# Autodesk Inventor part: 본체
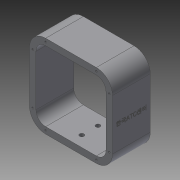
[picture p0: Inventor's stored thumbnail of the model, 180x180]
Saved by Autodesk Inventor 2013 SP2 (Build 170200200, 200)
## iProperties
Created: 2016-12
Part Number: 본체
Material: 일반
Document SubType Name: Modeling
Designer: mduedu
Density: 1 g/cm^3
Author: mduedu
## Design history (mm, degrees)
sketch "스케치1"
  geometry: L1 (-54, 50)-(-54, -44); L2 (-24, 80)-(70, 80); L3 (100, 50)-(100, -44); L4 (70, -74)-(-24, -74); A1 r 30 centre (-24, -44) between (-54, -44) and (-24, -74); A2 r 30 centre (70, 50) between (100, 50) and (70, 80); A3 r 30 centre (70, -44) between (70, -74) and (100, -44); A4 r 30 centre (-24, 50) between (-24, 80) and (-54, 50); 1 further point
  constraints: 8 end point, 8 point on circle, 8 tangent, 4 centre point, 3 equal radius, 2 perpendicular, 1 horizontal, 1 vertical
  dimensions: "d83" = 30 radius of A2; "d84" = 100 distance from line of L3 point (0, 0); "d85" = 154 distance between parallel lines of L4 L2; "d87" = 80 distance from line of point (0, 0) L2
extrude "돌출1" new body sketch "스케치1" stored distance "d3" = 70; taper "d4" = 0 deg
feature "쉘1" dims "d5" = 12
sketch "스케치10"
  geometry: 2 further points
  constraints: 1 coincident, 1 other
feature "엠보싱1" sketch "스케치10" dims "d61" = 0.5, "d62" = 0
sketch "스케치11"
  geometry: L1 (-42, -44)-(-42, 50) reference; L2 (-24, 68)-(70, 68) reference; L3 (88, 50)-(88, -44) reference; L4 (70, -62)-(-24, -62) reference; L5 (-24, -74)-(70, -74) reference; L6 (100, -44)-(100, 50) reference; L7 (70, 80)-(-24, 80) reference; L8 (-54, 50)-(-54, -44) reference; L9 (-24, 74)-(70, 74); L10 (94, 50)-(94, -44); L11 (70, -68)-(-24, -68); L12 (-48, -44)-(-48, 50); A1 r 18 centre (-24, -44) between (-42, -44) and (-24, -62) reference; A2 r 18 centre (-24, 50) between (-24, 68) and (-42, 50) reference; A3 r 18 centre (70, 50) between (88, 50) and (70, 68) reference; A4 r 18 centre (70, -44) between (70, -62) and (88, -44) reference; A5 r 30 centre (-24, -44) between (-54, -44) and (-24, -74) reference; A6 r 30 centre (70, -44) between (70, -74) and (100, -44) reference; A7 r 30 centre (70, 50) between (100, 50) and (70, 80) reference; A8 r 30 centre (-24, 50) between (-24, 80) and (-54, 50) reference; A9 r 24 centre (70, 50) between (94, 50) and (70, 74); A10 r 24 centre (70, -44) between (70, -68) and (94, -44); A11 r 24 centre (-24, -44) between (-48, -44) and (-24, -68); A12 r 24 centre (-24, 50) between (-24, 74) and (-48, 50); 8 further points
  constraints: 8 coincident, 8 end point, 8 point on circle, 4 centre point, 7 other
  dimensions: "d90" = 6 distance between parallel lines of L9 L7
hole "구멍3" sketch "스케치11" at (-24, 74), (-48, 50), (-48, -44), (-24, -68), (70, -68), (94, -44), (94, 50), (70, 74) diameter "d63" = 3.242; stored, may be unused: countersink angle "d67" = 90 deg, drill point angle "d69" = 120 deg; dims "d64" = 8.6, "d65" = 4, "d66" = 2, "d68" = 10.6
sketch "스케치12"
  geometry: L1 (24, -62)-(-70, -62) reference; L2 (-88, -44)-(-88, 50) reference; L3 (-70, 68)-(24, 68) reference; L4 (42, 50)-(42, -44) reference; L5 (54, -44)-(54, 50) reference; L6 (24, 80)-(-70, 80) reference; L7 (-100, 50)-(-100, -44) reference; L8 (-70, -74)-(24, -74) reference; L9 (-70, 74)-(24, 74); L10 (48, 50)-(48, -44); L11 (24, -68)-(-70, -68); L12 (-94, -44)-(-94, 50); A1 r 18 centre (24, -44) between (24, -62) and (42, -44) reference; A2 r 18 centre (-70, -44) between (-88, -44) and (-70, -62) reference; A3 r 18 centre (-70, 50) between (-70, 68) and (-88, 50) reference; A4 r 18 centre (24, 50) between (42, 50) and (24, 68) reference; A5 r 30 centre (24, -44) between (24, -74) and (54, -44) reference; A6 r 30 centre (24, 50) between (54, 50) and (24, 80) reference; A7 r 30 centre (-70, 50) between (-70, 80) and (-100, 50) reference; A8 r 30 centre (-70, -44) between (-100, -44) and (-70, -74) reference; A9 r 24 centre (24, 50) between (48, 50) and (24, 74); A10 r 24 centre (24, -44) between (24, -68) and (48, -44); A11 r 24 centre (-70, -44) between (-94, -44) and (-70, -68); A12 r 24 centre (-70, 50) between (-70, 74) and (-94, 50); 8 further points
  constraints: 8 coincident, 8 end point, 8 point on circle, 4 centre point, 7 other
  dimensions: "d91" = 6 distance between parallel lines of L9 L6
hole "구멍5" sketch "스케치12" at (-70, 74), (-94, 50), (-94, -44), (-70, -68), (24, -68), (48, -44), (48, 50), (24, 74) diameter "d70" = 3.242; stored, may be unused: countersink angle "d74" = 90 deg, drill point angle "d76" = 120 deg; dims "d71" = 8.6, "d72" = 4, "d73" = 2, "d75" = 10.6
sketch "스케치15"
  geometry: L1 (154.8, -35)-(-60.8, -35) reference; L2 (94, 0)-(0, 0) reference; L3 (0, -70)-(94, -70) reference; L4 (47, 0)-(47, -70); C1 r 4 at (47, -20); C2 r 4 at (47, -50); 1 further point
  constraints: 2 centre point, 2 end point, 2 midpoint, 1 point on line, 1 symmetric about line, 1 other
  dimensions: "d92" = 8 diameter of C1; "d93" = 15 distance from line of C1.centre L1
extrude "돌출6" cut sketch "스케치15" stored distance "d94" = 10; taper "d95" = 0 deg
node "솔리드1"
node "투영된 루프3"
node "투영된 루프4"
